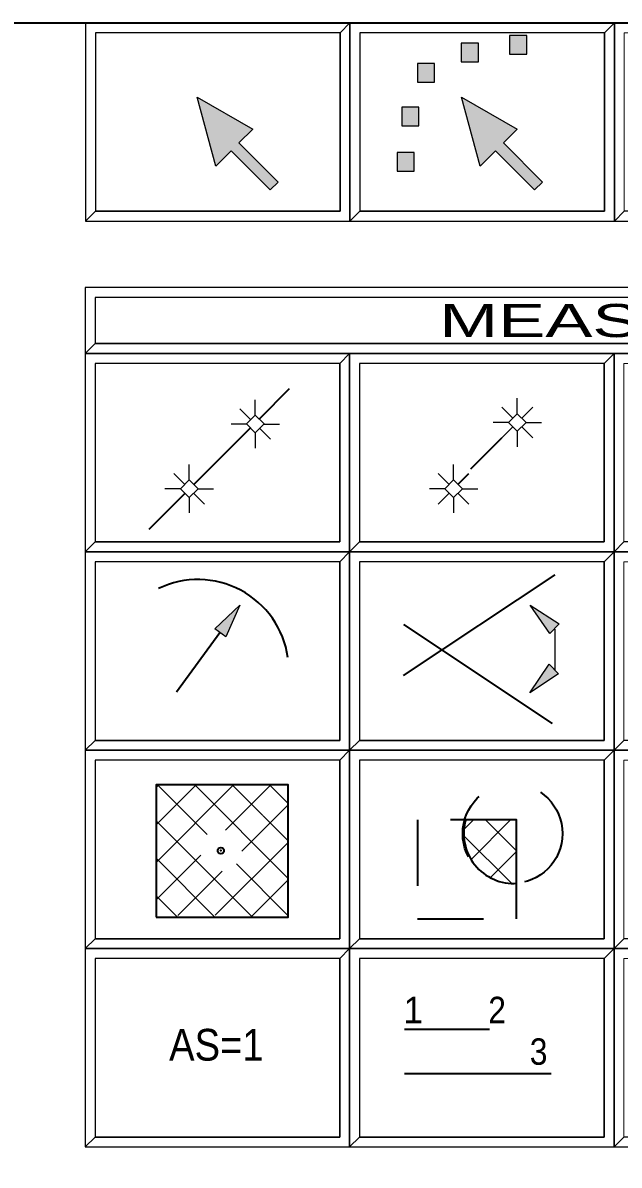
# Model space of a CAD drawing. Extents: x 95906.8 to 95923.6, y 90964.8 to 90972.8.
# Drawn here: x 95910.737 to 95911.64, y 90971.034 to 90972.762 of the extents above; entities that cross this region are included whole.
import ezdxf
from ezdxf.enums import TextEntityAlignment as Align

# ---------------------------------------------------------------- set-up
doc = ezdxf.new("R2010")
doc.units = 0
doc.header["$LTSCALE"] = 0.019
doc.header["$PDMODE"] = 32
doc.header["$PDSIZE"] = 0.0095
doc.linetypes.add('DOTTED', pattern=[1.5, 0.3, -1.2])
doc.linetypes.add('MEDIUM_DASHED', pattern=[4.5, 3, -1.5])
for name, color, linetype, lineweight in [('1', 7, 'Continuous', 25), ('11', 7, 'Continuous', 25), ('12', 7, 'Continuous', 25), ('2', 7, 'Continuous', 13), ('21', 7, 'Continuous', 25), ('3', 7, 'Continuous', 25), ('6', 7, 'Continuous', 35), ('7', 7, 'Continuous', 35)]:
    doc.layers.add(name, color=color, linetype=linetype, lineweight=lineweight)

msp = doc.modelspace()

# ---------------------------------------------------------------- hatches: boundary and pattern name
at = {"layer": '6'}
for points in [[(95911.4737, 90972.7144), (95911.4997, 90972.7144), (95911.4997, 90972.7427), (95911.4737, 90972.7427)], [(95911.4005, 90972.7026), (95911.4265, 90972.7026), (95911.4265, 90972.7309), (95911.4005, 90972.7309)], [(95911.3344, 90972.6719), (95911.3604, 90972.6719), (95911.3604, 90972.7002), (95911.3344, 90972.7002)], [(95911.0012, 90972.6492), (95911.0851, 90972.6007), (95911.0644, 90972.58), (95911.1235, 90972.5209), (95911.1115, 90972.5089), (95911.0524, 90972.568), (95911.0292, 90972.5448)], [(95911.4012, 90972.6492), (95911.4851, 90972.6007), (95911.4644, 90972.58), (95911.5235, 90972.5209), (95911.5115, 90972.5089), (95911.4524, 90972.568), (95911.4292, 90972.5448)], [(95911.3107, 90972.6058), (95911.3367, 90972.6058), (95911.3367, 90972.6341), (95911.3107, 90972.6341)], [(95911.3036, 90972.5373), (95911.3296, 90972.5373), (95911.3296, 90972.5656), (95911.3036, 90972.5656)], [(95911.0277, 90971.845), (95911.0655, 90971.881), (95911.0443, 90971.8333)], [(95911.5346, 90971.838), (95911.505, 90971.881), (95911.5488, 90971.8526)], [(95911.5479, 90971.7772), (95911.5045, 90971.7482), (95911.5335, 90971.7916)]]:
    msp.add_hatch(color=256, dxfattribs=at).paths.add_polyline_path(points)

# ---------------------------------------------------------------- linework, layer by layer
at = {"layer": '1'}
for points in [[(95910.8323, 90972.4617), (95911.2323, 90972.4617), (95911.2323, 90972.7617), (95910.8323, 90972.7617)], [(95911.2323, 90972.4617), (95911.6323, 90972.4617), (95911.6323, 90972.7617), (95911.2323, 90972.7617)], [(95911.6323, 90972.4617), (95912.0323, 90972.4617), (95912.0323, 90972.7617), (95911.6323, 90972.7617)], [(95910.8318, 90972.2615), (95912.4318, 90972.2615), (95912.4318, 90972.3615), (95910.8318, 90972.3615)], [(95910.8318, 90971.9615), (95911.2318, 90971.9615), (95911.2318, 90972.2615), (95910.8318, 90972.2615)], [(95911.2318, 90971.9615), (95911.6318, 90971.9615), (95911.6318, 90972.2615), (95911.2318, 90972.2615)], [(95911.6318, 90971.9615), (95912.0318, 90971.9615), (95912.0318, 90972.2615), (95911.6318, 90972.2615)], [(95910.8318, 90971.6615), (95911.2318, 90971.6615), (95911.2318, 90971.9615), (95910.8318, 90971.9615)], [(95911.2318, 90971.6615), (95911.6318, 90971.6615), (95911.6318, 90971.9615), (95911.2318, 90971.9615)], [(95911.6318, 90971.6615), (95912.0318, 90971.6615), (95912.0318, 90971.9615), (95911.6318, 90971.9615)], [(95910.8318, 90971.3615), (95911.2318, 90971.3615), (95911.2318, 90971.6615), (95910.8318, 90971.6615)], [(95911.2318, 90971.3615), (95911.6318, 90971.3615), (95911.6318, 90971.6615), (95911.2318, 90971.6615)], [(95911.6318, 90971.3615), (95912.0318, 90971.3615), (95912.0318, 90971.6615), (95911.6318, 90971.6615)], [(95910.8318, 90971.0615), (95911.2318, 90971.0615), (95911.2318, 90971.3615), (95910.8318, 90971.3615)], [(95911.2318, 90971.0615), (95911.6318, 90971.0615), (95911.6318, 90971.3615), (95911.2318, 90971.3615)], [(95911.6318, 90971.0615), (95912.0318, 90971.0615), (95912.0318, 90971.3615), (95911.6318, 90971.3615)]]:
    msp.add_lwpolyline(points, close=True, dxfattribs=at)
at = {"layer": '11'}
for points in [[(95910.8473, 90972.4767), (95911.2173, 90972.4767), (95911.2173, 90972.7467), (95910.8473, 90972.7467)], [(95911.2473, 90972.4767), (95911.6173, 90972.4767), (95911.6173, 90972.7467), (95911.2473, 90972.7467)], [(95911.2468, 90971.9765), (95911.6168, 90971.9765), (95911.6168, 90972.2465), (95911.2468, 90972.2465)], [(95910.8468, 90971.6765), (95911.2168, 90971.6765), (95911.2168, 90971.9465), (95910.8468, 90971.9465)], [(95911.2468, 90971.6765), (95911.6168, 90971.6765), (95911.6168, 90971.9465), (95911.2468, 90971.9465)], [(95910.8468, 90971.3765), (95911.2168, 90971.3765), (95911.2168, 90971.6465), (95910.8468, 90971.6465)], [(95911.2468, 90971.3765), (95911.6168, 90971.3765), (95911.6168, 90971.6465), (95911.2468, 90971.6465)], [(95910.8468, 90971.0765), (95911.2168, 90971.0765), (95911.2168, 90971.3465), (95910.8468, 90971.3465)], [(95911.2468, 90971.0765), (95911.6168, 90971.0765), (95911.6168, 90971.3465), (95911.2468, 90971.3465)]]:
    msp.add_lwpolyline(points, close=True, dxfattribs=at)
at = {"layer": '12'}
msp.add_lwpolyline([(95910.8468, 90971.9765), (95911.2168, 90971.9765), (95911.2168, 90972.2465), (95910.8468, 90972.2465)], close=True, dxfattribs=at)
at = {"layer": '2'}
for points in [[(95910.8323, 90972.7617), (95910.8323, 90972.4617), (95910.8473, 90972.4767), (95910.8473, 90972.7467), (95911.2173, 90972.7467), (95911.2323, 90972.7617)], [(95911.2323, 90972.7617), (95911.2323, 90972.4617), (95911.2473, 90972.4767), (95911.2473, 90972.7467), (95911.6173, 90972.7467), (95911.6323, 90972.7617)], [(95911.6323, 90972.7617), (95911.6323, 90972.4617), (95911.6473, 90972.4767), (95911.6473, 90972.7467), (95912.0173, 90972.7467), (95912.0323, 90972.7617)], [(95910.8318, 90972.3615), (95910.8318, 90972.2615), (95910.8468, 90972.2765), (95910.8468, 90972.3465), (95912.4168, 90972.3465), (95912.4318, 90972.3615)], [(95910.8318, 90972.2615), (95910.8318, 90971.9615), (95910.8468, 90971.9765), (95910.8468, 90972.2465), (95911.2168, 90972.2465), (95911.2318, 90972.2615)], [(95911.2318, 90972.2615), (95911.2318, 90971.9615), (95911.2468, 90971.9765), (95911.2468, 90972.2465), (95911.6168, 90972.2465), (95911.6318, 90972.2615)], [(95911.6318, 90972.2615), (95911.6318, 90971.9615), (95911.6468, 90971.9765), (95911.6468, 90972.2465), (95912.0168, 90972.2465), (95912.0318, 90972.2615)], [(95910.8318, 90971.9615), (95910.8318, 90971.6615), (95910.8468, 90971.6765), (95910.8468, 90971.9465), (95911.2168, 90971.9465), (95911.2318, 90971.9615)], [(95911.2318, 90971.9615), (95911.2318, 90971.6615), (95911.2468, 90971.6765), (95911.2468, 90971.9465), (95911.6168, 90971.9465), (95911.6318, 90971.9615)], [(95911.6318, 90971.9615), (95911.6318, 90971.6615), (95911.6468, 90971.6765), (95911.6468, 90971.9465), (95912.0168, 90971.9465), (95912.0318, 90971.9615)], [(95910.8318, 90971.6615), (95910.8318, 90971.3615), (95910.8468, 90971.3765), (95910.8468, 90971.6465), (95911.2168, 90971.6465), (95911.2318, 90971.6615)], [(95911.2318, 90971.6615), (95911.2318, 90971.3615), (95911.2468, 90971.3765), (95911.2468, 90971.6465), (95911.6168, 90971.6465), (95911.6318, 90971.6615)], [(95911.6318, 90971.6615), (95911.6318, 90971.3615), (95911.6468, 90971.3765), (95911.6468, 90971.6465), (95912.0168, 90971.6465), (95912.0318, 90971.6615)], [(95910.8318, 90971.3615), (95910.8318, 90971.0615), (95910.8468, 90971.0765), (95910.8468, 90971.3465), (95911.2168, 90971.3465), (95911.2318, 90971.3615)], [(95911.2318, 90971.3615), (95911.2318, 90971.0615), (95911.2468, 90971.0765), (95911.2468, 90971.3465), (95911.6168, 90971.3465), (95911.6318, 90971.3615)], [(95911.6318, 90971.3615), (95911.6318, 90971.0615), (95911.6468, 90971.0765), (95911.6468, 90971.3465), (95912.0168, 90971.3465), (95912.0318, 90971.3615)]]:
    msp.add_lwpolyline(points, close=True, dxfattribs=at)
at = {"layer": '21'}
msp.add_lwpolyline([(95910.8468, 90972.2765), (95912.4168, 90972.2765), (95912.4168, 90972.3465), (95910.8468, 90972.3465)], close=True, dxfattribs=at)
at = {"layer": '3', "lineweight": 13}
msp.add_line((95910.8324, 90971.6587), (95910.8324, 90971.0626), dxfattribs=at)
at = {"layer": '3'}
for points in [[(95910.8323, 90972.4617), (95911.2323, 90972.4617), (95911.2323, 90972.7617), (95911.2173, 90972.7467), (95911.2173, 90972.4767), (95910.8473, 90972.4767)], [(95911.2323, 90972.4617), (95911.6323, 90972.4617), (95911.6323, 90972.7617), (95911.6173, 90972.7467), (95911.6173, 90972.4767), (95911.2473, 90972.4767)], [(95911.6323, 90972.4617), (95912.0323, 90972.4617), (95912.0323, 90972.7617), (95912.0173, 90972.7467), (95912.0173, 90972.4767), (95911.6473, 90972.4767)], [(95910.8318, 90972.2615), (95912.4318, 90972.2615), (95912.4318, 90972.3615), (95912.4168, 90972.3465), (95912.4168, 90972.2765), (95910.8468, 90972.2765)], [(95910.8318, 90971.9615), (95911.2318, 90971.9615), (95911.2318, 90972.2615), (95911.2168, 90972.2465), (95911.2168, 90971.9765), (95910.8468, 90971.9765)], [(95911.2318, 90971.9615), (95911.6318, 90971.9615), (95911.6318, 90972.2615), (95911.6168, 90972.2465), (95911.6168, 90971.9765), (95911.2468, 90971.9765)], [(95911.6318, 90971.9615), (95912.0318, 90971.9615), (95912.0318, 90972.2615), (95912.0168, 90972.2465), (95912.0168, 90971.9765), (95911.6468, 90971.9765)], [(95910.8318, 90971.6615), (95911.2318, 90971.6615), (95911.2318, 90971.9615), (95911.2168, 90971.9465), (95911.2168, 90971.6765), (95910.8468, 90971.6765)], [(95911.2318, 90971.6615), (95911.6318, 90971.6615), (95911.6318, 90971.9615), (95911.6168, 90971.9465), (95911.6168, 90971.6765), (95911.2468, 90971.6765)], [(95911.6318, 90971.6615), (95912.0318, 90971.6615), (95912.0318, 90971.9615), (95912.0168, 90971.9465), (95912.0168, 90971.6765), (95911.6468, 90971.6765)], [(95910.8318, 90971.3615), (95911.2318, 90971.3615), (95911.2318, 90971.6615), (95911.2168, 90971.6465), (95911.2168, 90971.3765), (95910.8468, 90971.3765)], [(95911.2318, 90971.3615), (95911.6318, 90971.3615), (95911.6318, 90971.6615), (95911.6168, 90971.6465), (95911.6168, 90971.3765), (95911.2468, 90971.3765)], [(95911.6318, 90971.3615), (95912.0318, 90971.3615), (95912.0318, 90971.6615), (95912.0168, 90971.6465), (95912.0168, 90971.3765), (95911.6468, 90971.3765)], [(95910.8318, 90971.0615), (95911.2318, 90971.0615), (95911.2318, 90971.3615), (95911.2168, 90971.3465), (95911.2168, 90971.0765), (95910.8468, 90971.0765)], [(95911.2318, 90971.0615), (95911.6318, 90971.0615), (95911.6318, 90971.3615), (95911.6168, 90971.3465), (95911.6168, 90971.0765), (95911.2468, 90971.0765)], [(95911.6318, 90971.0615), (95912.0318, 90971.0615), (95912.0318, 90971.3615), (95912.0168, 90971.3465), (95912.0168, 90971.0765), (95911.6468, 90971.0765)]]:
    msp.add_lwpolyline(points, close=True, dxfattribs=at)
at = {"layer": '6'}
for p, q in [((95911.1405, 90972.208), (95911.0949, 90972.1624)), ((95911.0818, 90972.1493), (95910.9963, 90972.0637)), ((95910.9818, 90972.0493), (95910.928, 90971.9955)), ((95911.3134, 90971.7747), (95911.5425, 90971.9268)), ((95910.9697, 90971.7497), (95911.0354, 90971.8398)), ((95911.3134, 90971.8518), (95911.5384, 90971.7018)), ((95911.3148, 90971.2396), (95911.4434, 90971.2396)), ((95911.3148, 90971.1724), (95911.5368, 90971.1724))]:
    msp.add_line(p, q, dxfattribs=at)
at = {"layer": '6', "lineweight": 25}
for p, q in [((95911.0891, 90972.1682), (95911.0891, 90972.1916)), ((95911.4855, 90972.1705), (95911.4855, 90972.1939)), ((95911.0759, 90972.1549), (95911.0524, 90972.1549)), ((95911.1023, 90972.1549), (95911.1257, 90972.1549)), ((95911.4723, 90972.1572), (95911.4488, 90972.1572)), ((95911.4987, 90972.1572), (95911.5221, 90972.1572)), ((95911.0891, 90972.1417), (95911.0891, 90972.1183)), ((95911.4855, 90972.144), (95911.4855, 90972.1206)), ((95910.9891, 90972.0703), (95910.9891, 90972.0937)), ((95911.3891, 90972.0703), (95911.3891, 90972.0937)), ((95910.9759, 90972.057), (95910.9524, 90972.057)), ((95910.9891, 90972.0438), (95910.9891, 90972.0204)), ((95911.0023, 90972.057), (95911.0257, 90972.057)), ((95911.3759, 90972.057), (95911.3524, 90972.057)), ((95911.3891, 90972.0438), (95911.3891, 90972.0204)), ((95911.4023, 90972.057), (95911.4257, 90972.057)), ((95911.5421, 90971.8448), (95911.5421, 90971.7827))]:
    msp.add_line(p, q, dxfattribs=at)
at = {"layer": '6', "linetype": 'MEDIUM_DASHED', "lineweight": 13}
for p, q in [((95911.0825, 90972.1615), (95911.0659, 90972.1781)), ((95911.4789, 90972.1638), (95911.4623, 90972.1804)), ((95911.0957, 90972.1483), (95911.1123, 90972.1318)), ((95911.4921, 90972.1506), (95911.5087, 90972.1341)), ((95910.9825, 90972.0636), (95910.9659, 90972.0802)), ((95910.9957, 90972.0504), (95911.0123, 90972.0339)), ((95911.3957, 90972.0504), (95911.4123, 90972.0339))]:
    msp.add_line(p, q, dxfattribs=at)
at = {"layer": '6', "linetype": 'MEDIUM_DASHED', "lineweight": 25}
for p, q in [((95911.4921, 90972.1638), (95911.5087, 90972.1804)), ((95911.4789, 90972.1506), (95911.4623, 90972.1341)), ((95911.3825, 90972.0636), (95911.3659, 90972.0802)), ((95911.3825, 90972.0504), (95911.3659, 90972.0339))]:
    msp.add_line(p, q, dxfattribs=at)
at = {"layer": '6', "linetype": 'DOTTED'}
msp.add_line((95911.4154, 90972.0872), (95911.4623, 90972.1341), dxfattribs=at)
at = {"layer": '6', "linetype": 'MEDIUM_DASHED'}
msp.add_line((95911.3957, 90972.0636), (95911.4123, 90972.0802), dxfattribs=at)
at = {"layer": '6', "lineweight": 13}
for p, q in [((95910.9389, 90971.4919), (95911.0562, 90971.6092)), ((95910.9389, 90971.5485), (95910.9996, 90971.6092)), ((95910.9389, 90971.6051), (95910.943, 90971.6092)), ((95910.9409, 90971.6092), (95911.0163, 90971.5339)), ((95910.9975, 90971.6092), (95911.139, 90971.4677)), ((95911.044, 90971.5405), (95911.1127, 90971.6092)), ((95911.0541, 90971.6092), (95911.1007, 90971.5626)), ((95911.1106, 90971.6092), (95911.1389, 90971.5809)), ((95911.0687, 90971.5087), (95911.1389, 90971.5788)), ((95911.1012, 90971.5621), (95911.1389, 90971.5244)), ((95910.9389, 90971.5547), (95911.0832, 90971.4104)), ((95911.4029, 90971.5403), (95911.4192, 90971.5565)), ((95911.4157, 90971.4964), (95911.4758, 90971.5566)), ((95911.4378, 90971.5556), (95911.4847, 90971.5087)), ((95911.4046, 90971.5323), (95911.4762, 90971.4608)), ((95911.0286, 90971.4119), (95911.1389, 90971.5222)), ((95911.4439, 90971.4681), (95911.4845, 90971.5087)), ((95910.9389, 90971.4354), (95911.0065, 90971.503)), ((95910.9389, 90971.4981), (95911.0287, 90971.4083)), ((95910.9719, 90971.4118), (95911.0388, 90971.4787)), ((95911.0606, 90971.4895), (95911.1384, 90971.4117)), ((95911.0824, 90971.4092), (95911.1389, 90971.4657)), ((95910.9389, 90971.4415), (95910.9712, 90971.4092))]:
    msp.add_line(p, q, dxfattribs=at)
at = {"layer": '6', "lineweight": 25}
for points in [[(95911.4737, 90972.7144), (95911.4997, 90972.7144), (95911.4997, 90972.7427), (95911.4737, 90972.7427)], [(95911.4005, 90972.7026), (95911.4265, 90972.7026), (95911.4265, 90972.7309), (95911.4005, 90972.7309)], [(95911.3344, 90972.6719), (95911.3604, 90972.6719), (95911.3604, 90972.7002), (95911.3344, 90972.7002)], [(95911.0012, 90972.6492), (95911.0851, 90972.6007), (95911.0644, 90972.58), (95911.1235, 90972.5209), (95911.1115, 90972.5089), (95911.0524, 90972.568), (95911.0292, 90972.5448)], [(95911.4012, 90972.6492), (95911.4851, 90972.6007), (95911.4644, 90972.58), (95911.5235, 90972.5209), (95911.5115, 90972.5089), (95911.4524, 90972.568), (95911.4292, 90972.5448)], [(95911.3107, 90972.6058), (95911.3367, 90972.6058), (95911.3367, 90972.6341), (95911.3107, 90972.6341)], [(95911.3036, 90972.5373), (95911.3296, 90972.5373), (95911.3296, 90972.5656), (95911.3036, 90972.5656)], [(95911.4855, 90972.144), (95911.4988, 90972.1573), (95911.4855, 90972.1705), (95911.4722, 90972.1573)], [(95911.3891, 90972.0438), (95911.4024, 90972.0571), (95911.3891, 90972.0703), (95911.3758, 90972.0571)], [(95911.0277, 90971.845), (95911.0655, 90971.881), (95911.0443, 90971.8333)], [(95911.5346, 90971.838), (95911.505, 90971.881), (95911.5488, 90971.8526)], [(95911.5479, 90971.7772), (95911.5045, 90971.7482), (95911.5335, 90971.7916)]]:
    msp.add_lwpolyline(points, close=True, dxfattribs=at)
at = {"layer": '6', "lineweight": 13}
for points in [[(95911.0891, 90972.1417), (95911.1024, 90972.155), (95911.0891, 90972.1682), (95911.0758, 90972.155)], [(95910.9891, 90972.0438), (95911.0024, 90972.0571), (95910.9891, 90972.0703), (95910.9758, 90972.0571)]]:
    msp.add_lwpolyline(points, close=True, dxfattribs=at)
at = {"layer": '6'}
msp.add_lwpolyline([(95910.9389, 90971.4092), (95911.1389, 90971.4092), (95911.1389, 90971.6092), (95910.9389, 90971.6092)], close=True, dxfattribs=at)
at = {"layer": '6', "linetype": 'DOTTED'}
msp.add_lwpolyline([(95911.3344, 90971.4065), (95911.4844, 90971.4065), (95911.4844, 90971.5565), (95911.3344, 90971.5565)], close=True, dxfattribs=at)
at = {"layer": '6'}
msp.add_lwpolyline([(95911.4844, 90971.4558), (95911.4844, 90971.5565), (95911.4092, 90971.5565)], dxfattribs=at)
at = {"layer": '6', "linetype": 'DOTTED'}
msp.add_circle((95911.4783, 90971.5355), 0.0754, dxfattribs=at)
at = {"layer": '6'}
for centre, radius, start, end in [((95911.0024, 90971.7823), 0.1374, 8.167, 115.7914), ((95911.4798, 90971.5355), 0.0754, 163.6588, 274.1636)]:
    msp.add_arc(centre, radius, start, end, dxfattribs=at)
msp.add_point((95911.0369, 90971.5097), dxfattribs=at)
at = {"layer": '7'}
msp.add_lwpolyline([(95906.8323, 90972.7617), (95918.8323, 90972.7617), (95918.8323, 90964.7617), (95906.8323, 90964.7617)], close=True, dxfattribs=at)

# ---------------------------------------------------------------- texts
at = {"layer": '21', "width": 1.6}
msp.add_text('        MEASURE        ', height=0.04999, dxfattribs=at).set_placement((95911.6318, 90972.2865), align=Align.CENTER)
at = {"layer": '6'}
msp.add_text('1', height=0.04, dxfattribs=at).set_placement((95911.3281, 90971.2487), align=Align.CENTER)
at = {"layer": '6', "width": 0.9}
for s, height, p in [('2', 0.04, (95911.4549, 90971.2487)), ('AS=1', 0.048, (95911.0302, 90971.1921)), ('3', 0.04, (95911.5177, 90971.1858))]:
    msp.add_text(s, height=height, dxfattribs=at).set_placement(p, align=Align.CENTER)

doc.saveas('drawing.dxf')
